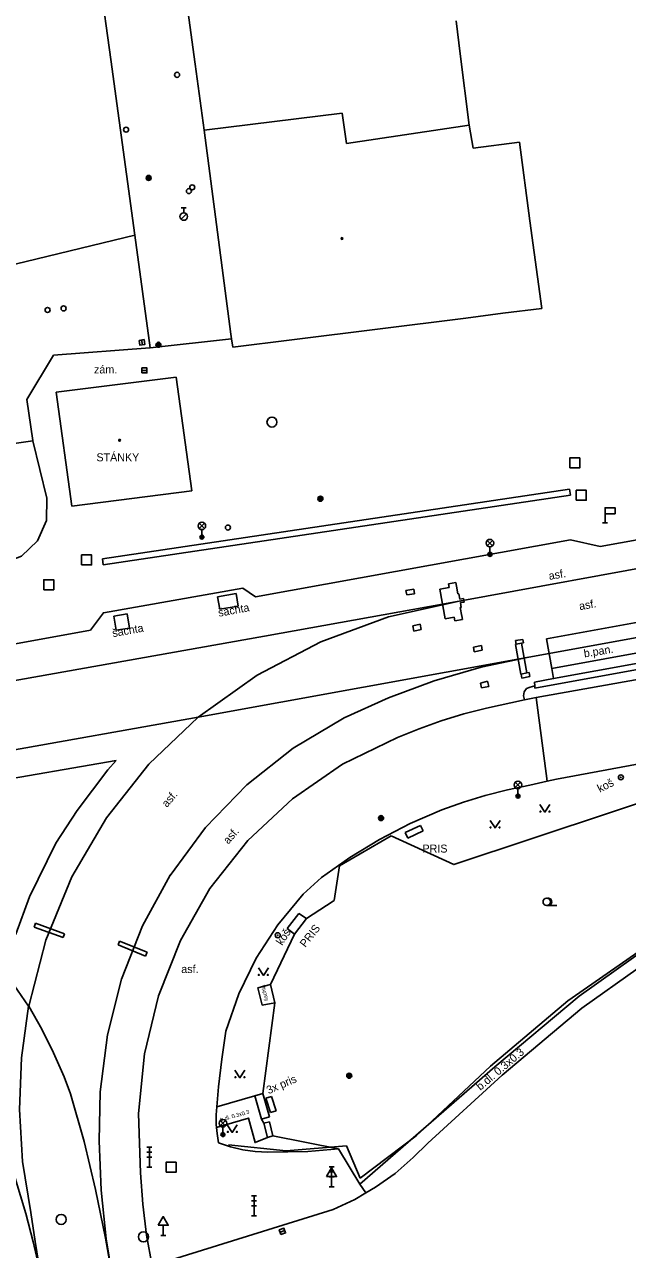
# Model space of a CAD drawing. Extents: x -599770 to -598493, y -1162076 to -1159209.
# Drawn here: x -599243.9 to -599213.8, y -1161220.6 to -1161159.4 of the extents above; entities that cross this region are included whole.
import ezdxf

# ---------------------------------------------------------------- set-up
doc = ezdxf.new("R2010")
doc.units = 0
doc.layers.add('Podklad', color=7, linetype='Continuous')

msp = doc.modelspace()

# ---------------------------------------------------------------- linework, layer by layer
at = {"layer": 'Podklad'}
for p, q in [((-599236.105, -1161168.512), (-599235.855, -1161168.512)), ((-599235.98, -1161168.762), (-599235.98, -1161168.512)), ((-599236.109, -1161169.086), (-599235.844, -1161168.821)), ((-599238.08, -1161175.117), (-599238.04, -1161175.363)), ((-599238.065, -1161176.64), (-599237.815, -1161176.64)), ((-599214.93, -1161183.8), (-599214.93, -1161184.25)), ((-599235.203, -1161184.54), (-599234.938, -1161184.275)), ((-599235.203, -1161184.275), (-599234.938, -1161184.54)), ((-599235.07, -1161184.595), (-599235.07, -1161184.97)), ((-599215.055, -1161184.25), (-599214.805, -1161184.25)), ((-599220.812, -1161185.4), (-599220.547, -1161185.135)), ((-599220.812, -1161185.135), (-599220.547, -1161185.4)), ((-599220.68, -1161185.455), (-599220.68, -1161185.83)), ((-599219.413, -1161197.48), (-599219.148, -1161197.215)), ((-599219.413, -1161197.215), (-599219.148, -1161197.48)), ((-599219.28, -1161197.535), (-599219.28, -1161197.91)), ((-599217.84, -1161203.378), (-599217.34, -1161203.378)), ((-599234.152, -1161214.39), (-599233.887, -1161214.125)), ((-599234.152, -1161214.125), (-599233.887, -1161214.39)), ((-599234.02, -1161214.445), (-599234.02, -1161214.82)), ((-599237.815, -1161215.45), (-599237.565, -1161215.45)), ((-599237.815, -1161215.7), (-599237.565, -1161215.7)), ((-599237.69, -1161216.45), (-599237.69, -1161215.45)), ((-599237.815, -1161215.95), (-599237.565, -1161215.95)), ((-599228.715, -1161216.43), (-599228.465, -1161216.43)), ((-599228.59, -1161217.43), (-599228.59, -1161216.43)), ((-599237.815, -1161216.45), (-599237.565, -1161216.45)), ((-599228.715, -1161216.68), (-599228.465, -1161216.68)), ((-599228.715, -1161216.93), (-599228.465, -1161216.93)), ((-599228.59, -1161216.921), (-599228.59, -1161217.43)), ((-599228.715, -1161217.43), (-599228.465, -1161217.43)), ((-599232.585, -1161217.88), (-599232.335, -1161217.88)), ((-599232.585, -1161218.13), (-599232.335, -1161218.13)), ((-599232.46, -1161218.88), (-599232.46, -1161217.88)), ((-599232.585, -1161218.38), (-599232.335, -1161218.38)), ((-599232.585, -1161218.88), (-599232.335, -1161218.88)), ((-599237, -1161219.351), (-599237, -1161219.86)), ((-599237.125, -1161219.86), (-599236.875, -1161219.86)), ((-599231.168, -1161219.701), (-599230.932, -1161219.619))]:
    msp.add_line(p, q, dxfattribs=at)
for points in [[(-599242.38, -1161140.68), (-599241.1, -1161149.4), (-599240.32, -1161155.9), (-599240.17, -1161157.12), (-599239.62, -1161161.1), (-599238.42, -1161169.88), (-599237.65, -1161175.51)], [(-599234.96, -1161164.64), (-599235.41, -1161161.33), (-599236.54, -1161153.03)], [(-599222.37, -1161159.18), (-599222.16, -1161160.82)], [(-599222.16, -1161160.82), (-599221.71, -1161164.39)], [(-599228.06, -1161163.79), (-599234.96, -1161164.64)], [(-599227.84, -1161165.3), (-599228.06, -1161163.79)], [(-599221.71, -1161164.39), (-599227.84, -1161165.3)], [(-599221.71, -1161164.39), (-599221.52, -1161165.53)], [(-599233.53, -1161175.48), (-599233.59, -1161175.06), (-599233.62, -1161174.82), (-599234.96, -1161164.64)], [(-599221.52, -1161165.53), (-599219.21, -1161165.24)], [(-599219.21, -1161165.24), (-599218.68, -1161169.16)], [(-599218.68, -1161169.16), (-599218.09, -1161173.54)], [(-599238.42, -1161169.88), (-599254.73, -1161173.83)], [(-599218.09, -1161173.54), (-599220.03, -1161173.78), (-599221.89, -1161174.02), (-599230.58, -1161175.11)], [(-599237.67, -1161175.51), (-599237.65, -1161175.51), (-599233.59, -1161175.06)], [(-599230.58, -1161175.11), (-599233.53, -1161175.48)], [(-599243.51, -1161180.14), (-599243.82, -1161178.09), (-599242.49, -1161175.87)], [(-599242.49, -1161175.87), (-599237.67, -1161175.51)], [(-599236.36, -1161176.97), (-599242.35, -1161177.72)], [(-599235.58, -1161182.65), (-599236.36, -1161176.97)], [(-599242.35, -1161177.72), (-599241.57, -1161183.42)], [(-599176.03, -1161179.84), (-599185.38, -1161181.48), (-599211.11, -1161186.14), (-599222.22, -1161188.17), (-599231.95, -1161189.91), (-599245.73, -1161192.37), (-599252.16, -1161193.54), (-599253.22, -1161193.73), (-599269.67, -1161197)], [(-599243.51, -1161180.15), (-599249.64, -1161181.02), (-599254.23, -1161182.89)], [(-599242.81, -1161183.03), (-599243.51, -1161180.15), (-599243.51, -1161180.14)], [(-599241.57, -1161183.42), (-599235.58, -1161182.65)], [(-599240.04, -1161186.06), (-599216.7, -1161182.57)], [(-599216.7, -1161182.57), (-599216.66, -1161182.87)], [(-599254.02, -1161197.32), (-599251.59, -1161196.88), (-599245.38, -1161195.76), (-599235.26, -1161193.96), (-599218.74, -1161190.97), (-599212.41, -1161189.82), (-599183.76, -1161184.68), (-599173.82, -1161182.81)], [(-599242.81, -1161183.03), (-599242.83, -1161184.14), (-599243.28, -1161185.15), (-599244.08, -1161185.92), (-599245.11, -1161186.32)], [(-599216.66, -1161182.87), (-599240, -1161186.36)], [(-599215.18, -1161185.44), (-599205.29, -1161183.65)], [(-599218.45, -1161192.21), (-599217.5, -1161192.04), (-599199.02, -1161188.68), (-599175.89, -1161184.51), (-599174.17, -1161184.2)], [(-599232.39, -1161187.95), (-599216.66, -1161185.1)], [(-599216.66, -1161185.1), (-599215.18, -1161185.44)], [(-599218.37, -1161192.98), (-599198.72, -1161189.48), (-599176.53, -1161185.48), (-599176.14, -1161187.62), (-599175.36, -1161187.47)], [(-599240, -1161186.36), (-599240.04, -1161186.06)], [(-599240.64, -1161189.62), (-599239.99, -1161188.75), (-599233.02, -1161187.52), (-599232.39, -1161187.95)], [(-599224.88, -1161187.63), (-599224.49, -1161187.57)], [(-599224.83, -1161187.86), (-599224.88, -1161187.63)], [(-599224.45, -1161187.8), (-599224.49, -1161187.57)], [(-599223.19, -1161187.57), (-599222.72, -1161187.48)], [(-599222.92, -1161189.05), (-599223.19, -1161187.57)], [(-599222.38, -1161187.24), (-599222.75, -1161187.31)], [(-599222.72, -1161187.48), (-599222.75, -1161187.31)], [(-599222.35, -1161187.42), (-599222.38, -1161187.24)], [(-599222.28, -1161187.81), (-599222.35, -1161187.42)], [(-599234.29, -1161187.95), (-599233.36, -1161187.79)], [(-599234.18, -1161188.57), (-599234.29, -1161187.95)], [(-599233.36, -1161187.79), (-599233.26, -1161188.41)], [(-599222.22, -1161188.17), (-599225.74, -1161188.95)], [(-599224.83, -1161187.86), (-599224.45, -1161187.8)], [(-599222.23, -1161187.81), (-599222.28, -1161187.81)], [(-599222.23, -1161187.81), (-599222.18, -1161188.07)], [(-599222.18, -1161188.07), (-599222, -1161188.03)], [(-599222.15, -1161188.24), (-599221.97, -1161188.21)], [(-599222.11, -1161188.48), (-599222.15, -1161188.24)], [(-599221.97, -1161188.21), (-599222, -1161188.03)], [(-599239.47, -1161188.92), (-599238.8, -1161188.8)], [(-599238.8, -1161188.8), (-599238.68, -1161189.51)], [(-599233.26, -1161188.41), (-599234.18, -1161188.57)], [(-599222.11, -1161188.48), (-599222.16, -1161188.49)], [(-599222.08, -1161188.9), (-599222.09, -1161188.91), (-599222.16, -1161188.49)], [(-599222.08, -1161188.9), (-599222.05, -1161189.09)], [(-599239.35, -1161189.62), (-599239.47, -1161188.92)], [(-599238.68, -1161189.51), (-599239.35, -1161189.62)], [(-599235.26, -1161193.96), (-599232.31, -1161191.87), (-599229.12, -1161190.2), (-599225.74, -1161188.95)], [(-599224.53, -1161189.4), (-599224.17, -1161189.31)], [(-599224.53, -1161189.4), (-599224.48, -1161189.67)], [(-599224.17, -1161189.31), (-599224.12, -1161189.58)], [(-599222.92, -1161189.05), (-599222.47, -1161188.97)], [(-599222.47, -1161188.97), (-599222.44, -1161189.15)], [(-599222.05, -1161189.09), (-599222.44, -1161189.15)], [(-599198.96, -1161188.97), (-599218.43, -1161192.51)], [(-599217.86, -1161190.05), (-599212.55, -1161189.09)], [(-599240.64, -1161189.62), (-599245.49, -1161190.5)], [(-599224.12, -1161189.58), (-599224.48, -1161189.67)], [(-599219.41, -1161190.14), (-599219.04, -1161190.08)], [(-599219.01, -1161190.25), (-599219.04, -1161190.08)], [(-599217.5, -1161192.04), (-599217.59, -1161191.53), (-599217.86, -1161190.05)], [(-599221.5, -1161190.47), (-599221.1, -1161190.39)], [(-599221.46, -1161190.7), (-599221.5, -1161190.47)], [(-599221.46, -1161190.7), (-599221.06, -1161190.62)], [(-599221.06, -1161190.62), (-599221.1, -1161190.39)], [(-599219.37, -1161190.32), (-599219.41, -1161190.14)], [(-599219.41, -1161190.33), (-599219.37, -1161190.32), (-599219.11, -1161190.27), (-599219.01, -1161190.25)], [(-599219.14, -1161191.81), (-599219.41, -1161190.33)], [(-599218.84, -1161191.75), (-599219.11, -1161190.27)], [(-599217.59, -1161191.53), (-599212.29, -1161190.56)], [(-599223.46, -1161192.15), (-599221.12, -1161191.47), (-599218.73, -1161190.96)], [(-599219.14, -1161191.81), (-599219.12, -1161191.81), (-599218.84, -1161191.75), (-599218.72, -1161191.73)], [(-599219.12, -1161191.81), (-599219.08, -1161192.01)], [(-599218.68, -1161191.93), (-599219.08, -1161192.01)], [(-599218.72, -1161191.73), (-599218.68, -1161191.93)], [(-599223.46, -1161192.15), (-599225.74, -1161192.99)], [(-599221.15, -1161192.26), (-599220.8, -1161192.17)], [(-599221.15, -1161192.26), (-599221.1, -1161192.5)], [(-599220.74, -1161192.43), (-599221.1, -1161192.5)], [(-599220.8, -1161192.17), (-599220.74, -1161192.43)], [(-599218.95, -1161193.09), (-599219.01, -1161192.9), (-599218.97, -1161192.7), (-599218.85, -1161192.54)], [(-599218.85, -1161192.54), (-599218.67, -1161192.46)], [(-599218.67, -1161192.46), (-599218.44, -1161192.4)], [(-599218.44, -1161192.4), (-599218.45, -1161192.21)], [(-599218.43, -1161192.51), (-599218.44, -1161192.4)], [(-599225.74, -1161192.99), (-599227.97, -1161193.99)], [(-599220.85, -1161193.51), (-599218.95, -1161193.09)], [(-599218.95, -1161193.09), (-599218.37, -1161192.98)], [(-599217.82, -1161197.17), (-599218.37, -1161192.98)], [(-599225.3, -1161194.98), (-599224.21, -1161194.54), (-599223.11, -1161194.14), (-599221.98, -1161193.8), (-599220.85, -1161193.51)], [(-599198.95, -1161193.64), (-599217.35, -1161197.07)], [(-599243.72, -1161208.41), (-599242.86, -1161205.11), (-599241.56, -1161201.95), (-599239.83, -1161199), (-599237.72, -1161196.32), (-599235.26, -1161193.96)], [(-599236.66, -1161201.87), (-599234.89, -1161199.48), (-599232.83, -1161197.35), (-599230.51, -1161195.51), (-599227.97, -1161193.99)], [(-599225.61, -1161199.9), (-599222.48, -1161201.33), (-599202.67, -1161194.75), (-599197.63, -1161193.92), (-599196.7, -1161196.51)], [(-599234.68, -1161202.52), (-599232.78, -1161200.13), (-599230.55, -1161198.05), (-599228.04, -1161196.32), (-599225.3, -1161194.98)], [(-599252.467, -1161198.392), (-599239.35, -1161196.13)], [(-599239.765, -1161196.592), (-599239.35, -1161196.13)], [(-599239.765, -1161196.592), (-599241.304, -1161198.632), (-599242.362, -1161200.265), (-599243.679, -1161202.936)], [(-599223.08, -1161198.59), (-599222, -1161198.21), (-599220.91, -1161197.87), (-599219.8, -1161197.59), (-599218.68, -1161197.36)], [(-599218.68, -1161197.36), (-599217.82, -1161197.17), (-599217.35, -1161197.07)], [(-599229.09, -1161201.97), (-599227.68, -1161200.97), (-599226.2, -1161200.07), (-599224.67, -1161199.28), (-599223.08, -1161198.59)], [(-599218.18, -1161198.335), (-599217.93, -1161198.71), (-599217.68, -1161198.335)], [(-599220.67, -1161199.125), (-599220.42, -1161199.5), (-599220.17, -1161199.125)], [(-599228.2, -1161201.4), (-599225.61, -1161199.9)], [(-599224.91, -1161199.73), (-599224.15, -1161199.37)], [(-599224.78, -1161200.01), (-599224.91, -1161199.73)], [(-599224.02, -1161199.65), (-599224.78, -1161200.01)], [(-599224.15, -1161199.37), (-599224.02, -1161199.65)], [(-599228.46, -1161203.12), (-599228.2, -1161201.4)], [(-599249.52, -1161201.85), (-599247.33, -1161203.81), (-599245.4, -1161206), (-599243.73, -1161208.41)], [(-599240.15, -1161212.69), (-599239.79, -1161209.84), (-599239.09, -1161207.06), (-599238.03, -1161204.39), (-599236.65, -1161201.86)], [(-599230.01, -1161202.81), (-599229.09, -1161201.97)], [(-599207.78, -1161201.88), (-599216.78, -1161208.14)], [(-599216.22, -1161207.91), (-599207.85, -1161201.95)], [(-599243.679, -1161202.936), (-599244.365, -1161204.81), (-599245.467, -1161203.711)], [(-599238.14, -1161216.74), (-599238.24, -1161213.76), (-599237.94, -1161210.79), (-599237.23, -1161207.89), (-599236.14, -1161205.12), (-599234.68, -1161202.52)], [(-599233.88, -1161209.66), (-599233.23, -1161207.79), (-599232.36, -1161206), (-599231.28, -1161204.34), (-599230.01, -1161202.81)], [(-599230.45, -1161204.8), (-599229.84, -1161204.03), (-599228.52, -1161203.16), (-599228.46, -1161203.12)], [(-599230.81, -1161204.52), (-599230.22, -1161203.77)], [(-599229.84, -1161204.03), (-599230.45, -1161204.8)], [(-599230.22, -1161203.77), (-599229.84, -1161204.03)], [(-599243.45, -1161204.45), (-599243.39, -1161204.26)], [(-599242, -1161204.98), (-599243.45, -1161204.45)], [(-599243.39, -1161204.26), (-599241.93, -1161204.79)], [(-599241.93, -1161204.79), (-599242, -1161204.98)], [(-599230.45, -1161204.8), (-599231.64, -1161207.33)], [(-599230.45, -1161204.8), (-599230.81, -1161204.52)], [(-599216.09, -1161208.51), (-599213.27, -1161206.5), (-599210.43, -1161204.52)], [(-599239.25, -1161205.34), (-599239.18, -1161205.15)], [(-599237.88, -1161205.9), (-599239.25, -1161205.34)], [(-599239.18, -1161205.15), (-599237.81, -1161205.71)], [(-599237.81, -1161205.71), (-599237.88, -1161205.9)], [(-599232.25, -1161206.495), (-599232, -1161206.87), (-599231.75, -1161206.495)], [(-599231.64, -1161207.33), (-599232.27, -1161207.48)], [(-599232.27, -1161207.48), (-599232.06, -1161208.36)], [(-599231.42, -1161208.23), (-599231.64, -1161207.33)], [(-599243.73, -1161208.41), (-599244.09, -1161210.98)], [(-599243.72, -1161208.41), (-599243.07, -1161209.56)], [(-599232.06, -1161208.36), (-599231.42, -1161208.23)], [(-599231.42, -1161208.23), (-599232.02, -1161212.77)], [(-599227.18, -1161217.29), (-599220.44, -1161211.43), (-599216.22, -1161207.91)], [(-599216.78, -1161208.14), (-599220.66, -1161211.4)], [(-599220.07, -1161211.86), (-599216.09, -1161208.51)], [(-599243.07, -1161209.56), (-599242.48, -1161210.74), (-599241.95, -1161211.94)], [(-599234.24, -1161212.44), (-599234.08, -1161211.05), (-599233.88, -1161209.66)], [(-599243.61, -1161218.72), (-599244.03, -1161216.16), (-599244.19, -1161213.57), (-599244.09, -1161210.98)], [(-599220.66, -1161211.4), (-599224.36, -1161214.89), (-599227.16, -1161217)], [(-599241.95, -1161211.94), (-599241.63, -1161212.78)], [(-599233.42, -1161211.605), (-599233.17, -1161211.98), (-599232.92, -1161211.605)], [(-599223.79, -1161215.25), (-599220.07, -1161211.86)], [(-599239.46, -1161222.44), (-599239.85, -1161220.03), (-599240.1, -1161217.59), (-599240.2, -1161215.14), (-599240.15, -1161212.69)], [(-599234.24, -1161212.44), (-599234.32, -1161213.44), (-599234.35, -1161213.84)], [(-599232.02, -1161212.77), (-599232.42, -1161212.89)], [(-599231.69, -1161213.94), (-599232.02, -1161212.77)], [(-599241.63, -1161212.78), (-599240.96, -1161215.16), (-599240.38, -1161217.57), (-599239.88, -1161220), (-599239.46, -1161222.44)], [(-599234.32, -1161213.44), (-599232.42, -1161212.89)], [(-599232.42, -1161212.89), (-599232.09, -1161214.05)], [(-599231.6, -1161212.91), (-599231.88, -1161213)], [(-599231.88, -1161213), (-599231.64, -1161213.72)], [(-599231.36, -1161213.63), (-599231.6, -1161212.91)], [(-599234.24, -1161215.23), (-599234.31, -1161214.77), (-599234.34, -1161214.47), (-599234.35, -1161214.31), (-599234.35, -1161213.84)], [(-599234.34, -1161214.47), (-599232.74, -1161214), (-599232.41, -1161215.22), (-599231.8, -1161214.96)], [(-599232.09, -1161214.05), (-599231.69, -1161213.94)], [(-599231.64, -1161213.72), (-599231.36, -1161213.63)], [(-599233.8, -1161214.335), (-599233.55, -1161214.71), (-599233.3, -1161214.335)], [(-599231.97, -1161214.25), (-599232.09, -1161214.05)], [(-599231.97, -1161214.25), (-599231.69, -1161214.18)], [(-599231.8, -1161214.96), (-599231.97, -1161214.25)], [(-599231.69, -1161214.18), (-599231.52, -1161214.89)], [(-599231.52, -1161214.89), (-599231.8, -1161214.96)], [(-599231.52, -1161214.89), (-599228.25, -1161215.54)], [(-599244.94, -1161215.23), (-599243.87, -1161218.77)], [(-599231.78, -1161215.7), (-599232.41, -1161215.67), (-599233.03, -1161215.58), (-599233.64, -1161215.43), (-599234.24, -1161215.23)], [(-599227.85, -1161215.38), (-599230.86, -1161215.64), (-599233.74, -1161215.34)], [(-599228.25, -1161215.54), (-599229.77, -1161215.67), (-599231.78, -1161215.7)], [(-599228.25, -1161215.54), (-599227.18, -1161217.29)], [(-599227.16, -1161217), (-599227.85, -1161215.38)], [(-599224.51, -1161215.97), (-599223.79, -1161215.25)], [(-599224.51, -1161215.97), (-599225.42, -1161216.76), (-599226.4, -1161217.45), (-599226.88, -1161217.73), (-599227.43, -1161218.06), (-599228.52, -1161218.57)], [(-599237.56, -1161221.38), (-599237.83, -1161219.84), (-599238.02, -1161218.3), (-599238.14, -1161216.74)], [(-599227.18, -1161217.29), (-599226.88, -1161217.73)], [(-599243.87, -1161218.77), (-599243.5, -1161220.18), (-599243.17, -1161221.61), (-599242.9, -1161223.06)], [(-599243.61, -1161218.72), (-599243.4, -1161220.17)], [(-599237.56, -1161221.38), (-599228.52, -1161218.57)], [(-599242.9, -1161223.05), (-599243.16, -1161221.61), (-599243.4, -1161220.17)]]:
    msp.add_lwpolyline(points, dxfattribs=at)
for points in [[(-599238.203, -1161175.137), (-599238.163, -1161175.383), (-599237.917, -1161175.343), (-599237.957, -1161175.097)], [(-599238.065, -1161176.765), (-599237.815, -1161176.765), (-599237.815, -1161176.515), (-599238.065, -1161176.515)], [(-599216.69, -1161181.51), (-599216.19, -1161181.51), (-599216.19, -1161181.01), (-599216.69, -1161181.01)], [(-599216.37, -1161183.13), (-599215.87, -1161183.13), (-599215.87, -1161182.63), (-599216.37, -1161182.63)], [(-599214.93, -1161183.8), (-599214.43, -1161183.8), (-599214.43, -1161183.5), (-599214.93, -1161183.5)], [(-599241.08, -1161186.36), (-599240.58, -1161186.36), (-599240.58, -1161185.86), (-599241.08, -1161185.86)], [(-599242.97, -1161187.6), (-599242.47, -1161187.6), (-599242.47, -1161187.1), (-599242.97, -1161187.1)], [(-599236.86, -1161216.7), (-599236.36, -1161216.7), (-599236.36, -1161216.2), (-599236.86, -1161216.2)], [(-599228.84, -1161216.921), (-599228.34, -1161216.921), (-599228.59, -1161216.488)], [(-599237.25, -1161219.351), (-599236.75, -1161219.351), (-599237, -1161218.918)], [(-599231.127, -1161219.819), (-599230.891, -1161219.737), (-599230.973, -1161219.501), (-599231.209, -1161219.583)]]:
    msp.add_lwpolyline(points, close=True, dxfattribs=at)
for centre, radius in [((-599236.31, -1161161.87), 0.125), ((-599238.86, -1161164.61), 0.125), ((-599237.73, -1161167.02), 0.125), ((-599237.73, -1161167.02), 0.1), ((-599237.73, -1161167.02), 0.075), ((-599237.73, -1161167.02), 0.05), ((-599237.73, -1161167.02), 0.025), ((-599235.55, -1161167.49), 0.125), ((-599235.72, -1161167.68), 0.125), ((-599235.98, -1161168.95), 0.188), ((-599228.07, -1161170.05), 0.045), ((-599228.07, -1161170.05), 0.0199), ((-599242.78, -1161173.62), 0.125), ((-599241.98, -1161173.54), 0.125), ((-599237.24, -1161175.36), 0.125), ((-599237.24, -1161175.36), 0.1), ((-599237.24, -1161175.36), 0.075), ((-599237.24, -1161175.36), 0.05), ((-599237.24, -1161175.36), 0.025), ((-599231.57, -1161179.22), 0.25), ((-599239.18, -1161180.13), 0.045), ((-599239.18, -1161180.13), 0.0199), ((-599229.15, -1161183.05), 0.125), ((-599229.15, -1161183.05), 0.1), ((-599229.15, -1161183.05), 0.075), ((-599229.15, -1161183.05), 0.05), ((-599229.15, -1161183.05), 0.025), ((-599235.07, -1161184.407), 0.188), ((-599233.77, -1161184.49), 0.125), ((-599235.07, -1161184.97), 0.1), ((-599235.07, -1161184.97), 0.0723), ((-599235.07, -1161184.97), 0.0438), ((-599220.68, -1161185.267), 0.188), ((-599220.68, -1161185.83), 0.1), ((-599220.68, -1161185.83), 0.0723), ((-599220.68, -1161185.83), 0.0438), ((-599214.14, -1161196.97), 0.125), ((-599219.28, -1161197.348), 0.188), ((-599214.14, -1161196.97), 0.0152), ((-599219.28, -1161197.91), 0.1), ((-599219.28, -1161197.91), 0.0723), ((-599219.28, -1161197.91), 0.0438), ((-599218.155, -1161198.685), 0.025), ((-599217.705, -1161198.685), 0.025), ((-599226.12, -1161199.01), 0.125), ((-599226.12, -1161199.01), 0.1), ((-599226.12, -1161199.01), 0.075), ((-599226.12, -1161199.01), 0.05), ((-599226.12, -1161199.01), 0.025), ((-599220.645, -1161199.475), 0.025), ((-599220.195, -1161199.475), 0.025), ((-599217.84, -1161203.19), 0.188), ((-599231.28, -1161204.86), 0.125), ((-599231.28, -1161204.86), 0.0152), ((-599232.225, -1161206.845), 0.025), ((-599231.775, -1161206.845), 0.025), ((-599233.395, -1161211.955), 0.025), ((-599232.945, -1161211.955), 0.025), ((-599227.71, -1161211.88), 0.125), ((-599227.71, -1161211.88), 0.1), ((-599227.71, -1161211.88), 0.075), ((-599227.71, -1161211.88), 0.05), ((-599227.71, -1161211.88), 0.025), ((-599234.02, -1161214.258), 0.188), ((-599234.02, -1161214.82), 0.1), ((-599234.02, -1161214.82), 0.0723), ((-599234.02, -1161214.82), 0.0438), ((-599233.775, -1161214.685), 0.025), ((-599233.325, -1161214.685), 0.025), ((-599242.1, -1161219.06), 0.25), ((-599237.99, -1161219.93), 0.25)]:
    msp.add_circle(centre, radius, dxfattribs=at)
msp.add_arc((-599217.777, -1161203.19), 0.188, 260.40593, 99.59407, dxfattribs=at)

# ---------------------------------------------------------------- texts
for s, p in [('zám.', (-599240.46, -1161176.79)), ('STÁNKY', (-599240.34, -1161181.18)), ('PRIS', (-599224.05, -1161200.73)), ('asf.', (-599236.1, -1161206.75))]:
    msp.add_text(s, height=0.4, dxfattribs=at).set_placement(p)
for s, height, rotation, p in [('asf.', 0.4, 10.06865, (-599217.71, -1161187.11)), ('asf.', 0.4, 10.06865, (-599216.19, -1161188.62)), ('šachta', 0.4, 10.47735, (-599234.22, -1161188.95)), ('šachta', 0.4, 10.47735, (-599239.51, -1161189.97)), ('b.pan.', 0.4, 9.08173, (-599215.96, -1161190.98)), ('koš', 0.4, 26.80066, (-599215.19, -1161197.74)), ('asf.', 0.4, 49.06812, (-599236.82, -1161198.5)), ('asf.', 0.4, 49.06812, (-599233.75, -1161200.34)), ('koš', 0.4, 57, (-599231.06, -1161205.4)), ('PRIS', 0.4, 52, (-599229.9, -1161205.5)), ('šachta', 0.2, 104, (-599231.75, -1161208.12)), ('b.dl. 0.3x0.3', 0.4, 40.08761, (-599221.16, -1161212.64)), ('3x pris', 0.4, 23.47865, (-599231.74, -1161212.81)), ('b.dl. 0.3x0.3', 0.2, 16, (-599234.13, -1161214.18))]:
    msp.add_text(s, height=height, rotation=rotation, dxfattribs=at).set_placement(p)

doc.saveas('drawing.dxf')
